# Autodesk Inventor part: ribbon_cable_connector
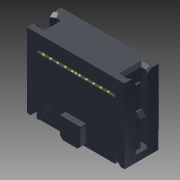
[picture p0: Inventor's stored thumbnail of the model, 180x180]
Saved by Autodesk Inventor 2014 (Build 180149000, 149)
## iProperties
Created: 2007-05
Part Number: ribbon_cable_connector
Document SubType Name: Modeling
Designer: floress
Density: 1 g/cm^3
Categories: <MemberInstance><Categories><Category DisplayName="" Mnemonic="CABLEANDHARNESS" InternalName="e4a7e005-5e42-4d16-b293-125e7f0d0512"><Category DisplayName="" Mne
Material: Generic
Appearance: Dark Gray
Author: floress
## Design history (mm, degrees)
sketch "Sketch1"
  geometry: L1 (-6.23, -1.5)-(-6.23, -2.1); L2 (-6.98, -1.5)-(-6.23, -1.5); L3 (6.98, -3)-(-6.98, -3); L4 (0, 3)-(0, -3); L5 (6.98, 1.5)-(6.98, -3); L6 (6.98, 1.5)-(6.23, 1.5); L7 (6.23, 1.5)-(6.23, 2.1); L8 (6.23, 2.1)-(6.98, 2.1); L9 (6.98, 3)-(6.98, 2.1); L10 (-6.98, 3)-(6.98, 3); L11 (-6.98, -1.5)-(-6.98, 3); L12 (-6.98, -3)-(-6.98, -2.1); L13 (-6.23, -2.1)-(-6.98, -2.1); 2 further points
  constraints: 26 end point, 8 parallel, 3 midpoint, 3 perpendicular, 2 horizontal, 1 coincident
extrude "Extrusion1" new body sketch "Sketch1" distance "d10" = 10.2; taper "d11" = 0 deg
sketch "Sketch2"
  geometry: L1 (5.18, 3.6)-(8.78, 3.6); L2 (8.78, 3.6)-(8.78, 0.5); L3 (8.28, 0)-(5.68, 0); L4 (5.18, 0.5)-(5.18, 3.6); L5 (5.18, 0.5)-(5.68, 0); L6 (8.78, 0.5)-(8.28, 0); 1 further point
  constraints: 12 end point, 2 parallel, 1 horizontal, 1 midpoint, 1 perpendicular
extrude "Extrusion2" join sketch "Sketch2" distance "d17" = 1; taper "d18" = 0 deg
sketch "Sketch3"
  geometry: L1 (-6.98, 0)-(6.98, 0); L2 (6.98, 1.22)-(6.98, 3.6); L3 (6.98, 3.6)-(7.23, 3.6); L4 (7.98, 2.1)-(7.98, 1.22); L5 (7.98, 1.22)-(6.98, 1.22); L6 (0, 10.2)-(0, 0); L7 (6.98, 10.2)-(-6.98, 10.2); L8 (7.23, 3.6)-(7.98, 2.1); L9 (-6.98, 1.22)-(-6.98, 3.6); L10 (-7.98, 2.1)-(-7.98, 1.22); L11 (-7.98, 1.22)-(-6.98, 1.22); L12 (-7.23, 3.6)-(-7.98, 2.1); L13 (-6.98, 3.6)-(-7.23, 3.6)
  constraints: 26 end point, 5 symmetric about line, 2 midpoint, 2 parallel, 2 perpendicular, 1 horizontal
extrude "Extrusion3" join sketch "Sketch3" stored distance "d26" = 1; taper "d27" = 0 deg
sketch "Sketch4"
  geometry: L1 (6.98, 3.6)-(7.23, 3.6); L2 (6.98, 5.263)-(6.98, 6.263); L3 (6.98, 6.263)-(7.23, 6.263); L4 (7.98, 5.263)-(6.98, 5.263); L5 (7.98, 5.513)-(7.98, 5.263); L6 (7.23, 6.263)-(7.98, 5.513); L7 (-6.98, 10.2)-(6.98, 10.2); L8 (-6.98, 5.263)-(-6.98, 6.263); L9 (-6.98, 6.263)-(-7.23, 6.263); L10 (-7.23, 6.263)-(-7.98, 5.513); L11 (-7.98, 5.513)-(-7.98, 5.263); L12 (-7.98, 5.263)-(-6.98, 5.263); 1 further point
  constraints: 24 end point, 2 parallel, 1 horizontal, 1 midpoint, 1 perpendicular
extrude "Extrusion4" join sketch "Sketch4" distance "d33" = 1; taper "d34" = 0 deg
sketch "Sketch5"
  geometry: L1 (1.3, 0)-(-1.3, 0); L2 (0, 0)-(0, -10.2); L3 (6.98, -10.2)-(-6.98, -10.2); L4 (-6.98, -6.263)-(-6.98, -5.263); L5 (-7.23, -6.263)-(-6.98, -6.263); L6 (-6.98, -5.263)-(-7.98, -5.263); L7 (-7.98, -5.263)-(-7.98, -5.513); L8 (-7.23, -6.263)-(-7.98, -5.513); L9 (7.23, -3.6)-(6.98, -3.6); L10 (6.98, -6.263)-(6.98, -5.263); L11 (7.23, -6.263)-(6.98, -6.263); L12 (7.23, -6.263)-(7.98, -5.513); L13 (7.98, -5.263)-(7.98, -5.513); L14 (6.98, -5.263)-(7.98, -5.263); L15 (6.98, -3.6)-(6.98, -1.22); L16 (7.98, -2.1)-(7.23, -3.6); L17 (6.98, -1.22)-(7.98, -1.22); L18 (7.98, -1.22)-(7.98, -2.1)
  constraints: 36 end point, 5 symmetric about line, 2 midpoint, 2 parallel, 1 horizontal, 1 perpendicular
  dimensions: "d35" = 1.663 distance between parallel lines of L9 L14; "d36" = 13.96 diameter of L10 L2 (= d41); "d37" = 1 distance of L10.start L10.end; "d38" = 1 distance of L10.end L13.start; "d39" = 0.25 distance of L11.start L10.start; "d40" = 0.25 distance of L13.start L12.end
extrude "Extrusion5" join sketch "Sketch5" distance "d42" = 1; taper "d43" = 0 deg
sketch "Sketch6"
  geometry: L1 (0.5, -10.2)-(2.5, -6.736); L2 (2.5, -6.736)-(4.5, -10.2); L3 (0.5, -10.2)-(4.5, -10.2); L4 (5.18, -9.7)-(5.18, -6.6); L5 (5.68, -10.2)-(5.18, -9.7)
  constraints: 10 end point, 2 equal length
extrude "Extrusion6" cut sketch "Sketch6" distance "d46" = 0.1; taper "d47" = 0 deg
sketch "Sketch7"
  geometry: L1 (4.705, 1.645)-(5.455, 1.645); L2 (5.455, 1.645)-(5.455, 0.895); L3 (5.455, 0.895)-(4.705, 0.895); L4 (6.98, 3)-(6.98, -1.5); L5 (4.705, 0.895)-(4.705, 1.645); L6 (4.705, -1.645)-(4.705, -0.895); L7 (5.08, 0.895)-(5.08, -0.895); L8 (4.705, -0.895)-(5.455, -0.895); L9 (5.455, -0.895)-(5.455, -1.645); L10 (5.455, -1.645)-(4.705, -1.645); L11 (6.23, -1.5)-(6.23, -2.1); L12 (6.48, -2.9)-(6.48, -3); L13 (6.98, -3)-(6.48, -3); L14 (6.98, -2.1)-(6.98, -3); L15 (6.23, -2.1)-(6.98, -2.1); 1 further point
  constraints: 30 end point, 7 equal length, 4 parallel, 3 midpoint, 3 perpendicular, 2 horizontal
extrude "Extrusion7" cut sketch "Sketch7" distance "d51" = 3; taper "d52" = 0 deg
chamfer "Chamfer1" distance "d53" = 0.5; stored, may be unused: second distance "d54" = 2, angle "d55" = 45 deg
pattern_linear "Rectangular Pattern1" dims "d58" = 2.54
workplane "Work Plane1"
sketch "Sketch8"
  geometry: L1 (6.98, 1.5)-(6.98, -3); L2 (6.23, 2.1)-(6.23, 1.5); L3 (6.23, 1.5)-(6.98, 1.5); L4 (6.98, 3)-(6.98, 2.1); L5 (6.98, 2.1)-(6.23, 2.1); L6 (7.11, -1.499)-(7.11, 1.499); L7 (7.961, 1.499)-(7.11, 1.499); L8 (7.961, -1.499)-(7.11, -1.499); L9 (8.665, 3.03)-(8.665, 1.03); L10 (8.665, 1.03)-(7.961, 1.499); L11 (8.665, -1.03)-(7.961, -1.499); L12 (8.665, -3.03)-(8.665, -1.03); L13 (-7.961, -1.499)-(-7.11, -1.499); L14 (-8.665, -1.03)-(-7.961, -1.499); L15 (-7.11, -1.499)-(-7.11, 1.499); L16 (-7.961, 1.499)-(-7.11, 1.499); L17 (-8.665, 1.03)-(-7.961, 1.499); L18 (-8.665, 3.03)-(-8.665, 1.03); L19 (0, 3)-(0, -3); L20 (-6.98, 3)-(6.98, 3); L21 (6.98, -3)-(-6.98, -3); L22 (-8.665, 3.03)-(8.665, 3.03); L23 (8.665, -3.03)-(-8.665, -3.03); L24 (-6.98, -1.5)-(-6.98, 3); L25 (-6.23, -2.1)-(-6.23, -1.5); L26 (-6.23, -1.5)-(-6.98, -1.5); L27 (-6.98, -2.1)-(-6.23, -2.1); L28 (-6.98, -3)-(-6.98, -2.1); L29 (-8.665, -3.03)-(-8.665, -1.03); 5 further points
  constraints: 58 end point, 6 symmetric about line, 5 midpoint, 3 parallel, 3 perpendicular, 1 coincident, 1 horizontal, 1 horizontal alignment
extrude "Extrusion8" join sketch "Sketch8" distance "d67" = 2.5; taper "d68" = 0 deg
sketch "Sketch9"
  geometry: L1 (6.99, 1.499)-(6.99, 3.03); L2 (7.11, 1.499)-(7.961, 1.499); L3 (7.11, -1.499)-(6.99, -1.499); L4 (6.99, -1.51)-(6.99, -1.499); L5 (6.24, -1.51)-(6.99, -1.51); L6 (6.24, -2.09)-(6.24, -1.51); L7 (6.99, -2.09)-(6.24, -2.09); L8 (6.99, -3.03)-(6.99, -2.09); L9 (7.961, -1.499)-(7.11, -1.499); L10 (7.961, -1.499)-(7.11, -1.499); L11 (-8.665, 3.03)-(-8.665, 1.03); L12 (8.665, -3.03)-(8.665, -1.03); L13 (8.665, -3.03)-(8.665, -1.03); L14 (8.665, -1.03)-(7.961, -1.499); L15 (8.665, -1.03)-(7.961, -1.499); L16 (-7.961, 1.499)-(-7.11, 1.499); L17 (-7.11, -1.499)-(-7.961, -1.499); L18 (-8.665, -1.03)-(-8.665, -3.03); L19 (-8.665, 1.03)-(-7.961, 1.499); L20 (-7.961, -1.499)-(-8.665, -1.03); L21 (-6.24, 1.51)-(-6.24, 2.09); L22 (-6.99, 1.51)-(-6.24, 1.51); L23 (-6.99, 2.09)-(-6.99, 3.03); L24 (-6.24, 2.09)-(-6.99, 2.09); L25 (8.665, 1.03)-(8.665, 3.03); L26 (7.961, 1.499)-(8.665, 1.03); L27 (7.11, 1.499)-(7.961, 1.499); L28 (7.961, 1.499)-(8.665, 1.03); L29 (8.665, 1.03)-(8.665, 3.03); L30 (7.11, 1.499)-(6.99, 1.499); L31 (-6.99, -3.03)-(-6.99, -1.499); L32 (-6.99, 1.499)-(-6.99, 1.51); L33 (-7.11, -1.499)-(-6.99, -1.499); L34 (-7.11, 1.499)-(-6.99, 1.499); L35 (-7.11, -1.499)-(-7.961, -1.499); L36 (-8.665, -1.03)-(-8.665, -3.03); L37 (-7.961, -1.499)-(-8.665, -1.03); L38 (-7.961, 1.499)-(-7.11, 1.499); L39 (-8.665, 1.03)-(-7.961, 1.499); L40 (-8.665, 3.03)-(-8.665, 1.03); L41 (8.665, -3.03)-(6.99, -3.03); L42 (-8.665, -3.03)-(-6.99, -3.03); L43 (-8.665, 3.03)-(-6.99, 3.03); L44 (6.99, 3.03)-(8.665, 3.03)
  constraints: 88 end point, 8 parallel, 6 perpendicular, 2 collinear, 2 horizontal
extrude "Extrusion9" join sketch "Sketch9" distance "d79" = 10.7; taper "d80" = 0 deg
sketch "Sketch10"
  geometry: L1 (-6.99, 0)-(-6.99, 1.21); L2 (-6.99, 1.21)-(-8.665, 1.21); L3 (-8.665, 0)-(-6.99, 0); L4 (-8.665, 1.21)-(-8.665, 0); L5 (6.99, 0)-(6.99, 1.21); L6 (8.665, 0)-(6.99, 0); L7 (8.665, 1.21)-(8.665, 0); L8 (6.99, 1.21)-(8.665, 1.21)
  constraints: 16 end point, 2 parallel, 1 horizontal, 1 perpendicular
extrude "Extrusion10" join sketch "Sketch10" stored distance "d83" = 6.06; taper "d84" = 0 deg
chamfer "Chamfer2" distance "d85" = 1; stored, may be unused: second distance "d86" = 2, angle "d87" = 45 deg
chamfer "Chamfer3" distance "d88" = 1.749; stored, may be unused: second distance "d89" = 2, angle "d90" = 45 deg
chamfer "Chamfer4" distance "d91" = 10.71; stored, may be unused: second distance "d92" = 0.03, angle "d93" = 45 deg
chamfer "Chamfer5" distance "d94" = 10.71; stored, may be unused: second distance "d95" = 0.03, angle "d96" = 45 deg
chamfer "Chamfer6" distance "d97" = 0.5; stored, may be unused: second distance "d98" = 0.03, angle "d99" = 45 deg
sketch "Sketch11"
  geometry: 1 further point
sketch "Sketch12"
  geometry: 1 further point
workpoint "Work Point1"
sketch "Sketch13"
  geometry: 1 further point
workpoint "Work Point2"
node "1"
node "2"
node "3"
node "4"
node "5"
node "6"
node "7"
node "8"
node "9"
node "10"
body "Solid1"
other parameters: "d9" = 13.96 [user parameter], "d25" = 13.96 [user parameter], "d41" = 13.96 [user parameter; used in 1 equation term], "d59" = 0.5, "d66" = 17.33 [user parameter], "d110" = 5.715 (computed from d111) [user parameter], "d111" = 17.33 [user parameter; used in 1 equation term]
